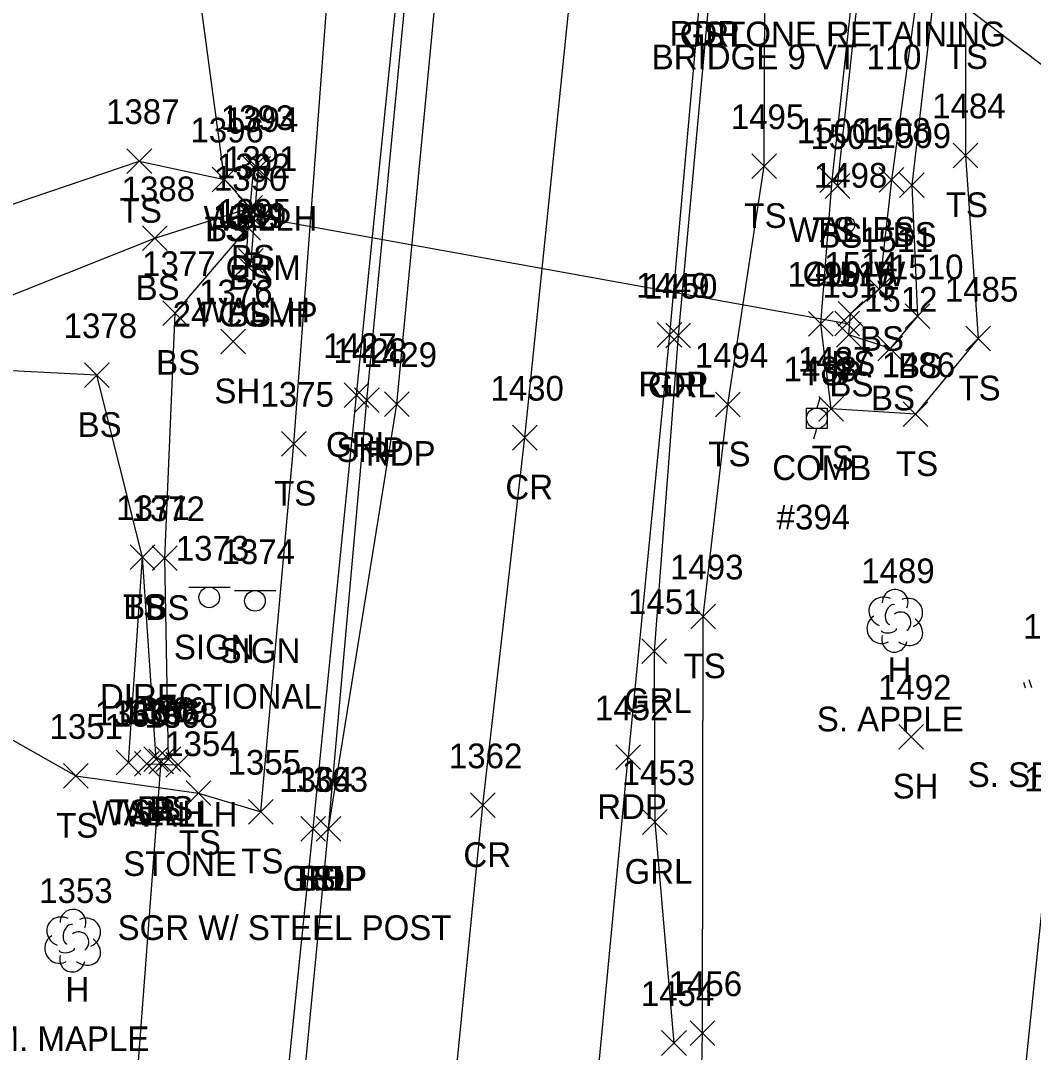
# Model space of a CAD drawing. Extents: x 1653908 to 1654393, y 539913 to 544256.
# Drawn here: x 1654015.1 to 1654097.1, y 541473.4 to 541556.9 of the extents above; entities that cross this region are included whole.
import ezdxf

# ---------------------------------------------------------------- set-up
doc = ezdxf.new("R2010")
doc.units = 0
for name, color, linetype in [('D_A', 7, 'Continuous'), ('D_C', 7, 'Continuous'), ('D_I', 7, 'Continuous'), ('D_TIC', 7, 'Continuous'), ('DCP', 7, 'Continuous'), ('DHW', 7, 'Continuous'), ('L_A', 7, 'Continuous'), ('L_C', 7, 'Continuous'), ('L_I', 7, 'Continuous'), ('L_TIC', 7, 'Continuous'), ('LELB', 7, 'Continuous'), ('LTC', 7, 'Continuous'), ('LTD', 7, 'Continuous'), ('LW', 7, 'Continuous'), ('P_A', 7, 'Continuous'), ('P_I', 7, 'Continuous'), ('P_TIC', 7, 'Continuous'), ('PET', 7, 'Continuous'), ('PRC', 7, 'Continuous'), ('PSP', 7, 'Continuous'), ('R_A', 7, 'Continuous'), ('R_I', 7, 'Continuous'), ('R_TIC', 7, 'Continuous'), ('RGR', 7, 'Continuous'), ('S_A', 7, 'Continuous'), ('S_C', 7, 'Continuous'), ('S_I', 7, 'Continuous'), ('SSGN', 7, 'Continuous'), ('U_A', 7, 'Continuous'), ('U_C', 7, 'Continuous'), ('U_I', 7, 'Continuous'), ('UP', 7, 'Continuous'), ('UPGW', 7, 'Continuous')]:
    doc.layers.add(name, color=color, linetype=linetype)

msp = doc.modelspace()

# ---------------------------------------------------------------- linework, layer by layer
at = {"layer": 'D_TIC'}
for points in [[(1654033.338, 541543.927), (1654035.338, 541545.927)], [(1654035.338, 541543.927), (1654033.338, 541545.927)], [(1654032.695, 541540.169), (1654034.695, 541542.169)], [(1654034.695, 541540.169), (1654032.695, 541542.169)], [(1654032.753, 541536.499), (1654034.753, 541538.499)], [(1654034.753, 541536.499), (1654032.753, 541538.499)], [(1654081.059, 541531.421), (1654083.059, 541533.421)], [(1654083.059, 541531.421), (1654081.059, 541533.421)], [(1654024.323, 541495.758), (1654026.323, 541497.758)], [(1654026.323, 541495.758), (1654024.323, 541497.758)], [(1654025.48, 541495.947), (1654027.48, 541497.947)], [(1654027.48, 541495.947), (1654025.48, 541497.947)], [(1654026.865, 541495.671), (1654028.865, 541497.671)], [(1654028.865, 541495.671), (1654026.865, 541497.671)]]:
    msp.add_lwpolyline(points, dxfattribs=at)
at = {"layer": 'DCP'}
for points in [[(1654033.695, 541541.169), (1654082.059, 541532.421)], [(1654020.208, 541413.754), (1654026.48, 541496.947)]]:
    msp.add_lwpolyline(points, dxfattribs=at)
at = {"layer": 'DHW'}
for points in [[(1654034.338, 541544.927), (1654033.753, 541537.499)], [(1654025.323, 541496.758), (1654027.865, 541496.671)]]:
    msp.add_lwpolyline(points, dxfattribs=at)
at = {"layer": 'L_TIC'}
for points in [[(1654023.718, 541544.57), (1654025.718, 541546.57)], [(1654025.718, 541544.57), (1654023.718, 541546.57)], [(1654090.642, 541545.028), (1654092.642, 541547.028)], [(1654092.642, 541545.028), (1654090.642, 541547.028)], [(1654033.003, 541544.075), (1654035.003, 541546.075)], [(1654035.003, 541544.075), (1654033.003, 541546.075)], [(1654074.324, 541544.155), (1654076.324, 541546.155)], [(1654076.324, 541544.155), (1654074.324, 541546.155)], [(1654030.605, 541543.072), (1654032.605, 541545.072)], [(1654032.605, 541543.072), (1654030.605, 541545.072)], [(1654030.605, 541543.072), (1654032.605, 541545.072)], [(1654032.605, 541543.072), (1654030.605, 541545.072)], [(1654079.833, 541543.016), (1654081.833, 541545.016)], [(1654081.833, 541543.016), (1654079.833, 541545.016)], [(1654079.833, 541543.016), (1654081.833, 541545.016)], [(1654081.833, 541543.016), (1654079.833, 541545.016)], [(1654084.639, 541543.05), (1654086.639, 541545.05)], [(1654086.639, 541543.05), (1654084.639, 541545.05)], [(1654080.282, 541542.549), (1654082.282, 541544.549)], [(1654082.282, 541542.549), (1654080.282, 541544.549)], [(1654086.299, 541542.618), (1654088.299, 541544.618)], [(1654088.299, 541542.618), (1654086.299, 541544.618)], [(1654032.701, 541540.772), (1654034.701, 541542.772)], [(1654034.701, 541540.772), (1654032.701, 541542.772)], [(1654032.701, 541540.772), (1654034.701, 541542.772)], [(1654034.701, 541540.772), (1654032.701, 541542.772)], [(1654032.539, 541539.162), (1654034.539, 541541.162)], [(1654034.539, 541539.162), (1654032.539, 541541.162)], [(1654032.539, 541539.162), (1654034.539, 541541.162)], [(1654034.539, 541539.162), (1654032.539, 541541.162)], [(1654024.976, 541538.317), (1654026.976, 541540.317)], [(1654026.976, 541538.317), (1654024.976, 541540.317)], [(1654032.381, 541536.159), (1654034.381, 541538.159)], [(1654034.381, 541536.159), (1654032.381, 541538.159)], [(1654083.652, 541534.194), (1654085.652, 541536.194)], [(1654085.652, 541534.194), (1654083.652, 541536.194)], [(1654026.633, 541532.26), (1654028.633, 541534.26)], [(1654028.633, 541532.26), (1654026.633, 541534.26)], [(1654081.33, 541532.197), (1654083.33, 541534.197)], [(1654083.33, 541532.197), (1654081.33, 541534.197)], [(1654081.33, 541532.197), (1654083.33, 541534.197)], [(1654083.33, 541532.197), (1654081.33, 541534.197)], [(1654086.744, 541531.995), (1654088.744, 541533.995)], [(1654088.744, 541531.995), (1654086.744, 541533.995)], [(1654078.92, 541531.394), (1654080.92, 541533.394)], [(1654080.92, 541531.394), (1654078.92, 541533.394)], [(1654081.181, 541530.501), (1654083.181, 541532.501)], [(1654083.181, 541530.501), (1654081.181, 541532.501)], [(1654031.311, 541529.954), (1654033.311, 541531.954)], [(1654033.311, 541529.954), (1654031.311, 541531.954)], [(1654091.665, 541530.187), (1654093.665, 541532.187)], [(1654093.665, 541530.187), (1654091.665, 541532.187)], [(1654084.547, 541529.377), (1654086.547, 541531.377)], [(1654086.547, 541529.377), (1654084.547, 541531.377)], [(1654020.279, 541527.225), (1654022.279, 541529.225)], [(1654022.279, 541527.225), (1654020.279, 541529.225)], [(1654071.402, 541524.844), (1654073.402, 541526.844)], [(1654073.402, 541524.844), (1654071.402, 541526.844)], [(1654079.766, 541524.513), (1654081.766, 541526.513)], [(1654081.766, 541524.513), (1654079.766, 541526.513)], [(1654086.603, 541524.065), (1654088.603, 541526.065)], [(1654088.603, 541524.065), (1654086.603, 541526.065)], [(1654036.227, 541521.669), (1654038.227, 541523.669)], [(1654038.227, 541521.669), (1654036.227, 541523.669)], [(1654023.971, 541512.486), (1654025.971, 541514.486)], [(1654025.971, 541512.486), (1654023.971, 541514.486)], [(1654023.971, 541512.486), (1654025.971, 541514.486)], [(1654025.971, 541512.486), (1654023.971, 541514.486)], [(1654025.771, 541512.404), (1654027.771, 541514.404)], [(1654027.771, 541512.404), (1654025.771, 541514.404)], [(1654069.4, 541507.686), (1654071.4, 541509.686)], [(1654071.4, 541507.686), (1654069.4, 541509.686)], [(1654086.252, 541497.943), (1654088.252, 541499.943)], [(1654088.252, 541497.943), (1654086.252, 541499.943)], [(1654025.077, 541496.129), (1654027.077, 541498.129)], [(1654027.077, 541496.129), (1654025.077, 541498.129)], [(1654026.089, 541496.132), (1654028.089, 541498.132)], [(1654028.089, 541496.132), (1654026.089, 541498.132)], [(1654026.089, 541496.132), (1654028.089, 541498.132)], [(1654028.089, 541496.132), (1654026.089, 541498.132)], [(1654022.842, 541495.864), (1654024.842, 541497.864)], [(1654024.842, 541495.864), (1654022.842, 541497.864)], [(1654018.572, 541494.774), (1654020.572, 541496.774)], [(1654020.572, 541494.774), (1654018.572, 541496.774)], [(1654028.506, 541493.378), (1654030.506, 541495.378)], [(1654030.506, 541493.378), (1654028.506, 541495.378)], [(1654033.561, 541491.875), (1654035.561, 541493.875)], [(1654035.561, 541491.875), (1654033.561, 541493.875)], [(1654037.793, 541490.482), (1654039.793, 541492.482)], [(1654039.793, 541490.482), (1654037.793, 541492.482)], [(1654069.344, 541473.938), (1654071.344, 541475.938)], [(1654071.344, 541473.938), (1654069.344, 541475.938)]]:
    msp.add_lwpolyline(points, dxfattribs=at)
at = {"layer": 'LELB'}
for points in [[(1654027.089, 541497.132), (1654026.771, 541513.404), (1654027.633, 541533.26), (1654033.539, 541540.162), (1654033.701, 541541.772), (1654031.605, 541544.072), (1654028.888, 541564.425), (1654033.422, 541588.392), (1654040.341, 541606.742), (1654044.362, 541608.705)], [(1654065.554, 541409.889), (1654067.543, 541432.122), (1654070.203, 541467.915), (1654070.344, 541474.938), (1654070.4, 541508.686), (1654072.402, 541525.844), (1654075.324, 541545.155), (1654075.449, 541572.998)], [(1654081.282, 541543.549), (1654083.43, 541563.529), (1654077.694, 541572.8)], [(1654089.692, 541564.521), (1654087.299, 541543.618), (1654087.744, 541532.995), (1654085.547, 541530.377), (1654082.181, 541531.501), (1654082.33, 541533.197)], [(1654088.511, 541564.849), (1654085.639, 541544.05), (1654084.652, 541535.194), (1654082.33, 541533.197)], [(1654006.915, 541502.932), (1654019.572, 541495.774), (1654029.506, 541494.378), (1654034.561, 541492.875), (1654037.227, 541522.669), (1654040.253, 541562.932)], [(1654111.103, 541539.428), (1654103.25, 541549.222), (1654091.637, 541558.031), (1654091.642, 541546.028), (1654092.665, 541531.187), (1654087.603, 541525.065), (1654080.766, 541525.513), (1654079.92, 541532.394), (1654080.833, 541544.016)], [(1653966.039, 541539.547), (1653986.615, 541536.835), (1654011.467, 541541.066), (1654024.718, 541545.57), (1654031.605, 541544.072)], [(1653967.053, 541529.902), (1653989.035, 541530.886), (1654011.842, 541533.704), (1654025.976, 541539.317), (1654033.701, 541541.772), (1654034.003, 541545.075)], [(1654033.381, 541537.159), (1654033.539, 541540.162)], [(1654027.089, 541497.132), (1654026.077, 541497.129), (1654024.971, 541513.486), (1654021.279, 541528.225), (1653993.606, 541529.624), (1653966.905, 541526.856)], [(1654023.842, 541496.864), (1654024.971, 541513.486)], [(1654031.439, 541442.607), (1654035.64, 541460.677), (1654038.793, 541491.482)], [(1654131.27, 541408.592), (1654106.78, 541414.135), (1654086.756, 541412.9), (1654094.608, 541453.803), (1654098.518, 541491.532)]]:
    msp.add_lwpolyline(points, dxfattribs=at)
at = {"layer": 'LTC'}
for p, q in [((1654096.329, 541503.362), (1654096.481, 541502.894)), ((1654096.784, 541503.579), (1654096.996, 541502.927))]:
    msp.add_line(p, q, dxfattribs=at)
at = {"layer": 'LTD'}
for p, q in [((1654085.898, 541508.382), (1654085.898, 541508.382)), ((1654085.898, 541508.382), (1654085.898, 541508.382)), ((1654019.3, 541482.482), (1654019.3, 541482.482)), ((1654019.3, 541482.482), (1654019.3, 541482.482))]:
    msp.add_line(p, q, dxfattribs=at)
for centre in [(1654085.945, 541509.816), (1654019.347, 541483.916)]:
    msp.add_arc(centre, 1.047, 335.52715, 180.95627, dxfattribs=at)
for centre, major_axis, ratio, start_param, end_param in [((1654085.106, 541509.049), (1.21, -0.512), 0.895232, 1.570796, 4.712389), ((1654086.94, 541508.966), (-1.141, -0.483), 0.949671, 1.570796, 4.712389), ((1654085.69, 541508.84), (-0.208, -0.792), 0.645439, 3.141593, 6.283185), ((1654086.398, 541508.215), (-0.5, 0.667), 0.989748, 3.141593, 6.283185), ((1654084.815, 541507.674), (0.584, -1.042), 0.959034, 3.141593, 6.283185), ((1654086.898, 541507.549), (-1.09, 0.792), 0.841452, 1.570796, 4.712389), ((1654085.44, 541507.632), (-0.625, -0.083), 0.423636, 0, 3.141593), ((1654085.899, 541506.882), (0.265, 1.061), 0.942809, 1.570796, 4.712389), ((1654018.508, 541483.149), (1.21, -0.512), 0.895232, 1.570796, 4.712389), ((1654020.342, 541483.066), (-1.141, -0.483), 0.949671, 1.570796, 4.712389), ((1654019.092, 541482.941), (-0.208, -0.792), 0.645439, 3.141593, 6.283185), ((1654019.8, 541482.316), (-0.5, 0.667), 0.989748, 3.141593, 6.283185), ((1654018.217, 541481.774), (0.584, -1.042), 0.959034, 3.141593, 6.283185), ((1654020.3, 541481.649), (-1.09, 0.792), 0.841452, 1.570796, 4.712389), ((1654018.842, 541481.732), (-0.625, -0.083), 0.423636, 0, 3.141593), ((1654019.3, 541480.982), (0.265, 1.061), 0.942809, 1.570796, 4.712389)]:
    msp.add_ellipse(centre, major_axis=major_axis, ratio=ratio, start_param=start_param, end_param=end_param, dxfattribs=at)
at = {"layer": 'LW'}
msp.add_lwpolyline([(1654080.833, 541544.016), (1654082.999, 541563.867), (1654077.35, 541572.356)], dxfattribs=at)
at = {"layer": 'P_TIC'}
for points in [[(1654066.659, 541530.505), (1654068.659, 541532.505)], [(1654068.659, 541530.505), (1654066.659, 541532.505)], [(1654042.139, 541525.202), (1654044.139, 541527.202)], [(1654044.139, 541525.202), (1654042.139, 541527.202)], [(1654044.583, 541524.885), (1654046.583, 541526.885)], [(1654046.583, 541524.885), (1654044.583, 541526.885)], [(1654054.938, 541522.167), (1654056.938, 541524.167)], [(1654056.938, 541522.167), (1654054.938, 541524.167)], [(1654063.32, 541496.282), (1654065.32, 541498.282)], [(1654065.32, 541496.282), (1654063.32, 541498.282)], [(1654063.32, 541496.282), (1654065.32, 541498.282)], [(1654065.32, 541496.282), (1654063.32, 541498.282)], [(1654051.537, 541492.395), (1654053.537, 541494.395)], [(1654053.537, 541492.395), (1654051.537, 541494.395)], [(1654039.035, 541490.488), (1654041.035, 541492.488)], [(1654041.035, 541490.488), (1654039.035, 541492.488)], [(1654039.035, 541490.488), (1654041.035, 541492.488)], [(1654041.035, 541490.488), (1654039.035, 541492.488)]]:
    msp.add_lwpolyline(points, dxfattribs=at)
at = {"layer": 'PET'}
for points in [[(1654002.711, 541022.85), (1654002.8, 541044.575), (1654003.387, 541071.89), (1654004.237, 541078.688), (1654006.743, 541130.143), (1654008.352, 541153.982), (1654010.069, 541183.44), (1654012.885, 541209.942), (1654016.448, 541249.52), (1654022.907, 541308.117), (1654024.639, 541328.517), (1654031.788, 541410.001), (1654035.81, 541442.822), (1654037.011, 541460.368), (1654040.035, 541491.488), (1654045.583, 541525.885), (1654049.594, 541568.112), (1654053.328, 541590.161), (1654054.271, 541598.349), (1654062.589, 541587.523), (1654071.875, 541577.056), (1654070.193, 541559.907), (1654067.659, 541531.505), (1654064.32, 541497.282)], [(1654026.617, 541021.773), (1654028.544, 541070.238), (1654031.495, 541127.981), (1654037.657, 541208.541), (1654042.526, 541248.324), (1654044.367, 541265.211), (1654043.732, 541271.442), (1654047.003, 541298.332), (1654052.518, 541346.465), (1654054.45, 541365.833), (1654058.245, 541433.285), (1654064.32, 541497.282)]]:
    msp.add_lwpolyline(points, dxfattribs=at)
at = {"layer": 'PRC'}
msp.add_lwpolyline([(1654015.219, 541022.422), (1654016.681, 541078.091), (1654019.776, 541129.034), (1654023.084, 541180.037), (1654025.544, 541208.787), (1654028.973, 541248.663), (1654033.814, 541299.535), (1654044.549, 541409.641), (1654048.398, 541449.608), (1654049.075, 541458.744), (1654052.537, 541493.395), (1654055.938, 541523.167), (1654060.179, 541564.47), (1654062.589, 541587.523)], dxfattribs=at)
at = {"layer": 'PSP'}
msp.add_lwpolyline([(1654040.035, 541491.488), (1654043.139, 541526.202), (1654047.189, 541568.342), (1654048.671, 541590.319)], dxfattribs=at)
at = {"layer": 'R_TIC'}
for points in [[(1654067.375, 541530.429), (1654069.375, 541532.429)], [(1654069.375, 541530.429), (1654067.375, 541532.429)], [(1654041.3, 541525.613), (1654043.3, 541527.613)], [(1654043.3, 541525.613), (1654041.3, 541527.613)], [(1654065.436, 541504.875), (1654067.436, 541506.875)], [(1654067.436, 541504.875), (1654065.436, 541506.875)], [(1654065.483, 541491.04), (1654067.483, 541493.04)], [(1654067.483, 541491.04), (1654065.483, 541493.04)], [(1654037.793, 541490.482), (1654039.793, 541492.482)], [(1654039.793, 541490.482), (1654037.793, 541492.482)], [(1654067.03, 541473.141), (1654069.03, 541475.141)], [(1654069.03, 541473.141), (1654067.03, 541475.141)]]:
    msp.add_lwpolyline(points, dxfattribs=at)
at = {"layer": 'RGR'}
for points in [[(1654038.793, 541491.482), (1654042.3, 541526.613), (1654046.528, 541568.325), (1654048.671, 541590.319), (1654049.721, 541602.05)], [(1654072.173, 541574.318), (1654070.947, 541559.825), (1654068.375, 541531.429), (1654066.436, 541505.875), (1654066.483, 541492.04), (1654068.03, 541474.141)]]:
    msp.add_lwpolyline(points, dxfattribs=at)
at = {"layer": 'SSGN'}
for p, q in [((1654028.734, 541511.064), (1654032.068, 541511.064)), ((1654032.437, 541510.78), (1654035.77, 541510.78)), ((1654030.381, 541510.231), (1654030.381, 541510.231)), ((1654034.083, 541509.947), (1654034.083, 541509.947))]:
    msp.add_line(p, q, dxfattribs=at)
for centre in [(1654030.381, 541510.231), (1654034.083, 541509.947)]:
    msp.add_circle(centre, 0.833, dxfattribs=at)
at = {"layer": 'UP'}
for p, q in [((1654079.854, 541526.401), (1654079.604, 541525.567)), ((1654078.77, 541523.901), (1654078.77, 541525.567)), ((1654078.77, 541525.567), (1654080.437, 541525.567)), ((1654080.437, 541525.567), (1654080.437, 541523.901)), ((1654079.604, 541524.734), (1654079.604, 541524.734)), ((1654080.437, 541523.901), (1654078.77, 541523.901)), ((1654079.354, 541523.067), (1654079.604, 541523.901))]:
    msp.add_line(p, q, dxfattribs=at)
msp.add_circle((1654079.604, 541524.734), 0.833, dxfattribs=at)
at = {"layer": 'UPGW'}
for radius in [0.625, 0.0833]:
    msp.add_circle((1654082.051, 541540.411), radius, dxfattribs=at)

# ---------------------------------------------------------------- texts
at = {"layer": 'D_A'}
for s, p in [('WALLH', (1654029.929, 541539.927)), ('P', (1654033.073, 541536.169)), ('WALLH', (1654029.344, 541532.499)), ('P', (1654081.437, 541527.421)), ('P', (1654025.858, 541491.947)), ('WALLH', (1654020.913, 541491.758)), ('WALLH', (1654023.456, 541491.671))]:
    msp.add_text(s, height=2, dxfattribs=at).set_placement(p)
at = {"layer": 'D_C'}
for s, p in [('CRM', (1654031.708, 541535.927)), ('24 CGMP', (1654027.42, 541532.169)), ('STONE', (1654023.409, 541487.671))]:
    msp.add_text(s, height=2, dxfattribs=at).set_placement(p)
at = {"layer": 'D_I'}
for s, p in [('1394', (1654031.646, 541547.927)), ('1392', (1654031.002, 541544.169)), ('1395', (1654031.061, 541540.499)), ('1515', (1654079.934, 541535.421)), ('1367', (1654022.583, 541499.758)), ('1366', (1654023.685, 541499.947)), ('1368', (1654025.125, 541499.671))]:
    msp.add_text(s, height=2, dxfattribs=at).set_placement(p)
at = {"layer": 'L_A'}
for s, p in [('TS', (1654090.047, 541553.031)), ('TS', (1654023.128, 541540.57)), ('TS', (1654090.051, 541541.028)), ('BS', (1654032.444, 541540.075)), ('TS', (1654073.734, 541540.155)), ('TS', (1654030.015, 541539.072)), ('BS', (1654030.046, 541539.072)), ('WALL', (1654077.322, 541539.016)), ('TS', (1654079.243, 541539.016)), ('BS', (1654084.08, 541539.05)), ('BS', (1654085.74, 541538.618)), ('BS', (1654079.723, 541538.549)), ('BS', (1654032.142, 541536.772)), ('BS', (1654032.142, 541536.772)), ('BS', (1654031.98, 541535.162)), ('BS', (1654031.98, 541535.162)), ('BS', (1654024.417, 541534.317)), ('BS', (1654031.822, 541532.159)), ('BS', (1654083.093, 541530.194)), ('BS', (1654026.074, 541528.26)), ('BS', (1654080.771, 541528.197)), ('BS', (1654080.771, 541528.197)), ('BS', (1654086.185, 541527.995)), ('TS', (1654078.329, 541527.394)), ('BS', (1654080.622, 541526.501)), ('TS', (1654091.074, 541526.187)), ('SH', (1654030.799, 541525.954)), ('BS', (1654083.988, 541525.377)), ('BS', (1654019.72, 541523.225)), ('TS', (1654070.812, 541520.844)), ('TS', (1654079.176, 541520.513)), ('TS', (1654086.012, 541520.065)), ('TS', (1654035.636, 541517.669)), ('TS', (1654023.381, 541508.486)), ('BS', (1654023.412, 541508.486)), ('BS', (1654025.212, 541508.404)), ('TS', (1654068.81, 541503.686)), ('H', (1654085.331, 541503.382)), ('SH', (1654085.74, 541493.943)), ('TS', (1654022.252, 541491.864)), ('BS', (1654024.518, 541492.129)), ('BS', (1654025.53, 541492.132)), ('BS', (1654025.53, 541492.132)), ('TS', (1654017.981, 541490.774)), ('TS', (1654027.915, 541489.378)), ('TS', (1654032.971, 541487.875)), ('TS', (1654037.202, 541486.482)), ('H', (1654018.733, 541477.482))]:
    msp.add_text(s, height=2, dxfattribs=at).set_placement(p)
at = {"layer": 'L_C'}
for s, p in [('STONE RETAINING', (1654070.393, 541554.867)), ('S. APPLE', (1654079.599, 541499.382)), ('S. SPRUCE', (1654091.826, 541494.875)), ('SGR W/ STEEL POST', (1654022.959, 541482.482)), ('M. MAPLE', (1654012.749, 541473.482))]:
    msp.add_text(s, height=2, dxfattribs=at).set_placement(p)
at = {"layer": 'L_I'}
for s, p in [('1484', (1654088.949, 541549.028)), ('1387', (1654022.025, 541548.57)), ('1393', (1654031.311, 541548.075)), ('1495', (1654072.631, 541548.155)), ('1396', (1654028.858, 541547.072)), ('1396', (1654028.858, 541547.072)), ('1500', (1654077.975, 541547.016)), ('1500', (1654077.975, 541547.016)), ('1508', (1654082.868, 541547.05)), ('1501', (1654079.077, 541546.549)), ('1509', (1654084.52, 541546.618)), ('1391', (1654031.575, 541544.772)), ('1391', (1654031.575, 541544.772)), ('1390', (1654030.76, 541543.162)), ('1390', (1654030.76, 541543.162)), ('1388', (1654023.284, 541542.317)), ('1389', (1654030.681, 541540.159)), ('1511', (1654083.094, 541538.194)), ('1377', (1654024.941, 541536.26)), ('1514', (1654080.204, 541536.197)), ('1514', (1654080.204, 541536.197)), ('1499', (1654077.219, 541535.394)), ('1510', (1654085.532, 541535.995)), ('1513', (1654080.056, 541534.501)), ('1376', (1654029.563, 541533.954)), ('1485', (1654089.972, 541534.187)), ('1512', (1654083.422, 541533.377)), ('1378', (1654018.586, 541531.225)), ('1494', (1654069.71, 541528.844)), ('1487', (1654078.073, 541528.513)), ('1486', (1654084.855, 541528.065)), ('1375', (1654034.534, 541525.669)), ('1371', (1654022.846, 541516.486)), ('1371', (1654022.846, 541516.486)), ('1372', (1654024.078, 541516.404)), ('1493', (1654067.708, 541511.686)), ('1489', (1654083.198, 541511.382)), ('1490', (1654096.322, 541506.875)), ('1492', (1654084.559, 541501.943)), ('1365', (1654021.102, 541499.864)), ('1370', (1654023.298, 541500.129)), ('1369', (1654024.342, 541500.132)), ('1369', (1654024.342, 541500.132)), ('1351', (1654017.446, 541498.774)), ('1354', (1654026.813, 541497.378)), ('1355', (1654031.869, 541495.875)), ('1364', (1654036.053, 541494.482)), ('1491', (1654096.393, 541494.532)), ('1353', (1654016.607, 541485.482)), ('1456', (1654067.597, 541477.938))]:
    msp.add_text(s, height=2, dxfattribs=at).set_placement(p)
at = {"layer": 'P_A'}
for s, p in [('RDP', (1654067.681, 541554.907)), ('RDP', (1654065.147, 541526.505)), ('SHP', (1654040.674, 541521.202)), ('RDP', (1654043.071, 541520.885)), ('CR', (1654054.371, 541518.167)), ('RDP', (1654061.808, 541492.282)), ('RDP', (1654061.808, 541492.282)), ('CR', (1654050.97, 541488.395)), ('SHP', (1654037.571, 541486.488)), ('RDP', (1654037.523, 541486.488))]:
    msp.add_text(s, height=2, dxfattribs=at).set_placement(p)
at = {"layer": 'P_I'}
for s, p in [('1449', (1654064.958, 541534.505)), ('1428', (1654040.446, 541529.202)), ('1429', (1654042.883, 541528.885)), ('1430', (1654053.159, 541526.167)), ('1452', (1654061.627, 541500.282)), ('1452', (1654061.627, 541500.282)), ('1362', (1654049.797, 541496.395)), ('1363', (1654037.295, 541494.488)), ('1363', (1654037.295, 541494.488))]:
    msp.add_text(s, height=2, dxfattribs=at).set_placement(p)
at = {"layer": 'R_A'}
for p in [(1654068.49, 541554.825), (1654065.918, 541526.429), (1654039.843, 541521.613), (1654063.979, 541500.875), (1654064.027, 541487.04), (1654036.336, 541486.482)]:
    msp.add_text('GRL', height=2, dxfattribs=at).set_placement(p)
at = {"layer": 'R_I'}
for s, p in [('1450', (1654065.595, 541534.429)), ('1427', (1654039.607, 541529.613)), ('1451', (1654064.31, 541508.875)), ('1364', (1654036.053, 541494.482)), ('1453', (1654063.791, 541495.04)), ('1454', (1654065.337, 541477.141))]:
    msp.add_text(s, height=2, dxfattribs=at).set_placement(p)
at = {"layer": 'S_A'}
for p in [(1654027.519, 541505.211), (1654031.221, 541504.926)]:
    msp.add_text('SIGN', height=2, dxfattribs=at).set_placement(p)
at = {"layer": 'S_C'}
for s, p in [('BRIDGE 9 VT 110', (1654066.224, 541553.002)), ('DIRECTIONAL', (1654021.527, 541501.211))]:
    msp.add_text(s, height=2, dxfattribs=at).set_placement(p)
at = {"layer": 'S_I'}
for s, p in [('1373', (1654027.669, 541513.211)), ('1374', (1654031.371, 541512.926))]:
    msp.add_text(s, height=2, dxfattribs=at).set_placement(p)
at = {"layer": 'U_A'}
for s, p in [('GUYW', (1654078.445, 541535.411)), ('COMB', (1654075.99, 541519.734))]:
    msp.add_text(s, height=2, dxfattribs=at).set_placement(p)
at = {"layer": 'U_C'}
msp.add_text('#394', height=2, dxfattribs=at).set_placement((1654076.344, 541515.734))
at = {"layer": 'U_I'}
for s, p in [('1498', (1654079.359, 541543.411)), ('1488', (1654076.911, 541527.734))]:
    msp.add_text(s, height=2, dxfattribs=at).set_placement(p)

doc.saveas('drawing.dxf')
